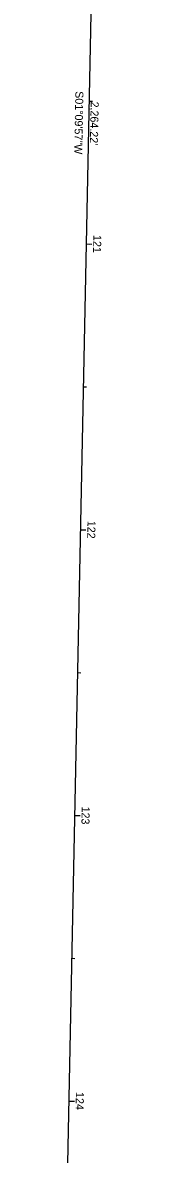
# Model space of a CAD drawing. Extents: x 1392427 to 1392809, y 435950 to 439080.
# Drawn here: x 1392717.3 to 1392763.4, y 436725.5 to 437121.5 of the extents above; entities that cross this region are included whole.
import ezdxf

# ---------------------------------------------------------------- set-up
doc = ezdxf.new("R2010")
doc.units = 0
for name, color, linetype in [('Default', 7, 'Continuous'), ('LT_X_PullBox', 7, 'Continuous'), ('PV_X_Curb', 7, 'Continuous'), ('PV_X_Driveway', 7, 'Continuous'), ('RD_X_Fence', 7, 'Continuous'), ('RW_X_CL', 7, 'Continuous'), ('RW_X_CL_100_Bearings', 7, 'Continuous'), ('RW_X_CL_100_Distances', 7, 'Continuous'), ('RW_X_CL_100_Stations', 7, 'Continuous'), ('SG_X_Poles', 7, 'Continuous'), ('SV_X_Mon_Cells_Found', 7, 'Continuous'), ('UT_X_Gas', 7, 'Continuous'), ('UT_X_Sanitary_Cells', 7, 'Continuous')]:
    doc.layers.add(name, color=color, linetype=linetype)

msp = doc.modelspace()

# ---------------------------------------------------------------- linework, layer by layer
at = {"layer": 'Default'}
msp.add_line((1392763.4, 438217.67), (1392717.33, 435953.92), dxfattribs=at)
at = {"layer": 'PV_X_Curb'}
for p, q in [((1392739.51, 437044.02), (1392740.71, 437043.99)), ((1392737.48, 436944.04), (1392738.68, 436944.01)), ((1392735.44, 436844.06), (1392736.64, 436844.03)), ((1392733.41, 436744.08), (1392734.61, 436744.05))]:
    msp.add_line(p, q, dxfattribs=at)
at = {"layer": 'RW_X_CL'}
msp.add_line((1392763.4, 438217.67), (1392717.33, 435953.92), dxfattribs=at)
msp.add_line((1392763.4, 438217.67), (1392717.33, 435953.92), dxfattribs=at)
at = {"layer": 'RW_X_CL_100_Stations'}
for p, q in [((1392740.53, 437094.01), (1392741.73, 437093.98)), ((1392739.51, 437044.02), (1392741.51, 437043.97)), ((1392738.5, 436994.03), (1392739.7, 436994)), ((1392737.48, 436944.04), (1392739.48, 436944)), ((1392736.46, 436894.05), (1392737.66, 436894.02)), ((1392735.44, 436844.06), (1392737.44, 436844.02)), ((1392734.43, 436794.07), (1392735.63, 436794.04)), ((1392733.41, 436744.08), (1392735.41, 436744.04))]:
    msp.add_line(p, q, dxfattribs=at)
at = {"layer": 'SV_X_Mon_Cells_Found'}
for p, q in [((1392739.51, 437044.02), (1392740.71, 437043.99)), ((1392737.48, 436944.04), (1392738.68, 436944.01)), ((1392735.44, 436844.06), (1392736.64, 436844.03)), ((1392733.41, 436744.08), (1392734.61, 436744.05))]:
    msp.add_line(p, q, dxfattribs=at)

# ---------------------------------------------------------------- texts
at = {"layer": 'LT_X_PullBox'}
msp.add_text("2,264.22'", height=2.8, rotation=268.834, dxfattribs=at).set_placement((1392741.15, 437093.88))
at = {"layer": 'PV_X_Driveway'}
msp.add_text("2,264.22'", height=2.8, rotation=268.834, dxfattribs=at).set_placement((1392741.15, 437093.88))
at = {"layer": 'RD_X_Fence'}
msp.add_text("2,264.22'", height=2.8, rotation=268.834, dxfattribs=at).set_placement((1392741.15, 437093.88))
at = {"layer": 'RW_X_CL_100_Bearings'}
msp.add_text('S01°09\'57"W', height=2.8, rotation=268.834, dxfattribs=at).set_placement((1392735.8, 437097.51))
at = {"layer": 'RW_X_CL_100_Distances'}
msp.add_text("2,264.22'", height=2.8, rotation=268.834, dxfattribs=at).set_placement((1392741.15, 437093.88))
at = {"layer": 'RW_X_CL_100_Stations'}
for s, p in [('121', (1392742.08, 437047.19)), ('122', (1392740.04, 436947.2)), ('123', (1392738.01, 436847.2)), ('124', (1392735.98, 436747.31))]:
    msp.add_text(s, height=2.8, rotation=268.834, dxfattribs=at).set_placement(p)
at = {"layer": 'SG_X_Poles'}
msp.add_text('S01°09\'57"W', height=2.8, rotation=268.834, dxfattribs=at).set_placement((1392735.8, 437097.51))
at = {"layer": 'UT_X_Gas'}
msp.add_text('S01°09\'57"W', height=2.8, rotation=268.834, dxfattribs=at).set_placement((1392735.8, 437097.51))
at = {"layer": 'UT_X_Sanitary_Cells'}
msp.add_text('S01°09\'57"W', height=2.8, rotation=268.834, dxfattribs=at).set_placement((1392735.8, 437097.51))

doc.saveas('drawing.dxf')
